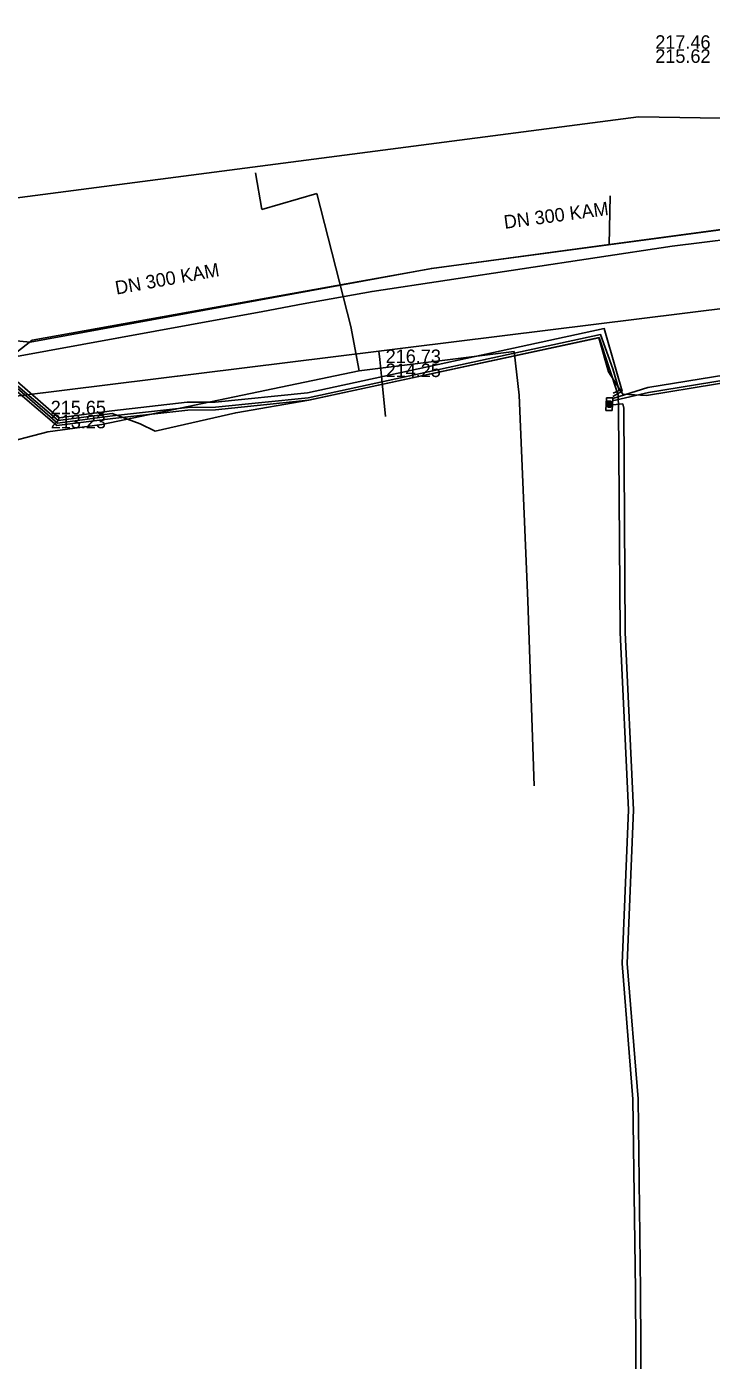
# Model space of a CAD drawing. Extents: x -596024 to -594475, y -1163820 to -1161957.
# Drawn here: x -595845.8 to -595805.3, y -1162955 to -1162876 of the extents above; entities that cross this region are included whole.
import ezdxf

# ---------------------------------------------------------------- set-up
doc = ezdxf.new("R2010")
doc.units = 0
for name, color, linetype in [('Level 1', 7, 'Continuous'), ('Vrstva 1', 7, 'Continuous'), ('Vrstva 12', 7, 'Continuous'), ('Vrstva 13', 7, 'Continuous'), ('Vrstva 16', 7, 'Continuous'), ('Vrstva 25', 7, 'Continuous'), ('Vrstva 28', 7, 'Continuous'), ('Vrstva 4', 7, 'Continuous'), ('Vrstva 42', 7, 'Continuous'), ('Vrstva 43', 7, 'Continuous'), ('Vrstva 55', 7, 'Continuous'), ('Vrstva 9', 7, 'Continuous')]:
    doc.layers.add(name, color=color, linetype=linetype)

# ---------------------------------------------------------------- blocks, each defined once
blk = doc.blocks.new('NN620')
at = {"layer": 'Vrstva 28'}
for points in [[(0.752, 0.004), (-0.748, 0.004)], [(-0.748, 0.004), (-0.748, -0.746)], [(0.752, -0.746), (0.752, 0.004)], [(-0.748, -0.746), (0.752, -0.746)], [(0.368, -0.18), (-0.376, -0.18)], [(-0.376, -0.18), (-0.376, -0.558)], [(-0.376, -0.558), (0.368, -0.558)], [(0.321, -0.227), (-0.329, -0.227)], [(-0.329, -0.227), (-0.329, -0.51)], [(-0.329, -0.51), (0.321, -0.51)], [(0.274, -0.274), (-0.281, -0.274)], [(-0.281, -0.274), (-0.281, -0.463)], [(-0.281, -0.463), (0.274, -0.463)], [(0.227, -0.321), (-0.234, -0.321)], [(-0.234, -0.321), (-0.234, -0.416)], [(-0.234, -0.416), (0.227, -0.416)], [(-0.193, -0.369), (0.185, -0.369)], [(0.227, -0.416), (0.227, -0.321)], [(0.274, -0.463), (0.274, -0.274)], [(0.321, -0.51), (0.321, -0.227)], [(0.368, -0.558), (0.368, -0.18)]]:
    blk.add_lwpolyline(points, dxfattribs=at)

msp = doc.modelspace()

# ---------------------------------------------------------------- linework, layer by layer
at = {"layer": 'Level 1'}
for points in [[(-596024.42, -1162921.712), (-596001.15, -1162890.66), (-595962.42, -1162895.72), (-595924.28, -1162893.96), (-595884.16, -1162890.98), (-595845.62, -1162894.68), (-595821.86, -1162890.31), (-595800.89, -1162887.52), (-595750.86, -1162888.83), (-595701.41, -1162888.47), (-595679.74, -1162860.44)], [(-595811.34, -1162888.91), (-595811.27, -1162886.02)]]:
    msp.add_lwpolyline(points, dxfattribs=at)
at = {"layer": 'Vrstva 1'}
for p, q in [((-595809.6, -1162881.33), (-595884.18, -1162891.07)), ((-595757.85, -1162882.25), (-595809.6, -1162881.33))]:
    msp.add_line(p, q, dxfattribs=at)
at = {"layer": 'Vrstva 13'}
msp.add_lwpolyline([(-595880.521, -1162931.197), (-595876.77, -1162924.18), (-595860.51, -1162904.47), (-595848.94, -1162895.98), (-595831.837, -1162892.858), (-595829.46, -1162892.422), (-595825.38, -1162891.68), (-595807.59, -1162889), (-595802.16, -1162888.33)], dxfattribs=at)
at = {"layer": 'Vrstva 16'}
for points in [[(-595873.17, -1162923.5), (-595869.94, -1162919.26), (-595860.83, -1162908.34), (-595858.96, -1162906.51), (-595848.86, -1162898.18), (-595824.97, -1162895.21), (-595823.24, -1162895), (-595801.28, -1162892.27)], [(-595824.59, -1162899.1), (-595824.82, -1162896.7), (-595824.92, -1162895.71), (-595824.97, -1162895.21)]]:
    msp.add_lwpolyline(points, dxfattribs=at)
at = {"layer": 'Vrstva 25'}
for p, q in [((-595832.289, -1162884.652), (-595831.897, -1162886.829)), ((-595831.897, -1162886.829), (-595828.644, -1162885.869)), ((-595826.625, -1162893.749), (-595828.644, -1162885.869)), ((-595826.144, -1162896.387), (-595826.625, -1162893.749)), ((-595816.949, -1162895.236), (-595826.144, -1162896.387)), ((-595816.664, -1162897.821), (-595816.949, -1162895.236)), ((-595826.144, -1162896.387), (-595841.393, -1162899.568)), ((-595816.158, -1162910.015), (-595816.664, -1162897.821)), ((-595841.393, -1162899.568), (-595844.583, -1162900.003)), ((-595844.583, -1162900.003), (-595850.855, -1162901.638)), ((-595815.772, -1162920.976), (-595816.158, -1162910.015))]:
    msp.add_line(p, q, dxfattribs=at)
at = {"layer": 'Vrstva 42'}
for points in [[(-595811.105, -1162897.896), (-595810.556, -1162897.582), (-595810.933, -1162896.279), (-595811.625, -1162893.884), (-595829.204, -1162897.682), (-595834.668, -1162898.24), (-595836.319, -1162898.25), (-595840.788, -1162898.761), (-595843.923, -1162899.163), (-595847.506, -1162896.059), (-595849.103, -1162892.459)], [(-595811.092, -1162897.711), (-595810.745, -1162897.557), (-595811.107, -1162896.267), (-595811.835, -1162894.236), (-595829.156, -1162897.978), (-595834.652, -1162898.54), (-595836.301, -1162898.55), (-595840.752, -1162899.059), (-595844.017, -1162899.477), (-595847.754, -1162896.241), (-595849.389, -1162892.555)], [(-595803.228, -1162978.24), (-595809.609, -1162978.365), (-595810.333, -1162975.664), (-595810.497, -1162974.755), (-595809.65, -1162971.384), (-595809.77, -1162950.863), (-595809.92, -1162939.544), (-595810.56, -1162931.516), (-595810.19, -1162922.401), (-595810.68, -1162911.898), (-595810.77, -1162898.597), (-595810.798, -1162897.824), (-595811.93, -1162894.41), (-595829.123, -1162898.125), (-595833.452, -1162898.873), (-595838.23, -1162899.96), (-595839.105, -1162899.519), (-595840.77, -1162898.91), (-595843.97, -1162899.32), (-595847.7, -1162896.157), (-595849.237, -1162892.569)], [(-595691.91, -1162893.65), (-595692.881, -1162893.397), (-595699.61, -1162893), (-595717.299, -1162893.93), (-595724.614, -1162893.49), (-595734.606, -1162893.25), (-595739.698, -1162893.13), (-595749.428, -1162893.07), (-595757.29, -1162892.88), (-595768.056, -1162893.127), (-595768.158, -1162899.522), (-595768.351, -1162899.552), (-595768.524, -1162899.534), (-595768.356, -1162893.109), (-595772.591, -1162892.55), (-595782.301, -1162892.66), (-595789.464, -1162892.71), (-595801.275, -1162893.186), (-595801.376, -1162896.122), (-595809.044, -1162897.379), (-595811.105, -1162898.02)], [(-595801.371, -1162896.425), (-595808.996, -1162897.675), (-595811.128, -1162898.17)], [(-595810.417, -1162975.448), (-595810.076, -1162975.4), (-595810.19, -1162974.765), (-595809.35, -1162971.42), (-595809.47, -1162950.86), (-595809.62, -1162939.53), (-595810.26, -1162931.51), (-595809.89, -1162922.4), (-595810.38, -1162911.89), (-595810.47, -1162898.59), (-595810.525, -1162898.345), (-595811.12, -1162898.394)]]:
    msp.add_lwpolyline(points, dxfattribs=at)
at = {"layer": 'Vrstva 55'}
msp.add_lwpolyline([(-595849.6, -1162892.39), (-595849.49, -1162892.65), (-595847.88, -1162896.36), (-595844.04, -1162899.63), (-595840.74, -1162899.2), (-595836.29, -1162898.71), (-595834.65, -1162898.69), (-595829.14, -1162898.13), (-595811.95, -1162894.42), (-595811.37, -1162896.45), (-595810.53, -1162897.76), (-595809.11, -1162897.85), (-595800.94, -1162896.51), (-595800.86, -1162894.36), (-595800.93, -1162893.75)], dxfattribs=at)
at = {"layer": 'Vrstva 9'}
for points in [[(-595800.88, -1162887.5), (-595811.17, -1162888.881), (-595811.336, -1162888.903), (-595821.83, -1162890.31)], [(-595821.83, -1162890.31), (-595829.33, -1162891.659), (-595845.52, -1162894.57)], [(-595845.52, -1162894.57), (-595848.315, -1162896.748), (-595860.65, -1162906.36)]]:
    msp.add_lwpolyline(points, dxfattribs=at)

# ---------------------------------------------------------------- block references
at = {"layer": 'Vrstva 43', "xscale": 0.5000000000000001, "yscale": 0.4999999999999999, "rotation": -91.99999999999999}
msp.add_blockref('NN620', (-595811.134, -1162898.363), dxfattribs=at)

# ---------------------------------------------------------------- texts
at = {"layer": 'Vrstva 12'}
for rotation, p in [(7.62034, (-595817.516, -1162887.971)), (10.19865, (-595840.517, -1162891.87))]:
    msp.add_text('DN 300 KAM', height=0.8, rotation=rotation, dxfattribs=at).set_placement(p)
for s, p in [('216.73', (-595824.571, -1162895.922)), ('214.25', (-595824.571, -1162896.754)), ('215.65', (-595844.412, -1162898.959)), ('213.23', (-595844.412, -1162899.791))]:
    msp.add_text(s, height=0.8, dxfattribs=at).set_placement(p)
at = {"layer": 'Vrstva 4'}
for s, p in [('217.46', (-595808.6, -1162877.298)), ('215.62', (-595808.6, -1162878.13))]:
    msp.add_text(s, height=0.8, dxfattribs=at).set_placement(p)

doc.saveas('drawing.dxf')
